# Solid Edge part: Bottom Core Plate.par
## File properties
Author: davee
Template: Normal.par
Last saved by: davee
Revision: 15
Application: Solid Edge
Accuracy: 0.990
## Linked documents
Top Core Plate.par
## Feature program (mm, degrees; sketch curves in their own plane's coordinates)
sketch for "ExtrudedProtrusion_3" plane through (0, 2.945, -20) normal (0, 0, -1) x-axis (-1, 0, 0)
extrude "ExtrudedProtrusion_3" add finite 40 along +normal
sketch for "Hole_3" plane through (0, 0, 0) normal (0, 0, 1) x-axis (1, 0, 0)
  hole centre (-58, 26.745) bore radius 2.4585
hole "Hole_3" finite  VBottomAngle = 118 deg; ThreadDepth = 2 mm
sketch for "unnamed Hole 1" plane through (0, 0, 0) normal (0, 0, 1) x-axis (1, 0, 0)
  hole centre (-58, -22.4) bore radius 2.4585
hole "unnamed Hole 1" finite
sketch for "unnamed Hole 2" plane through (0, 0, 0) normal (0, 0, 1) x-axis (1, 0, 0)
  hole centre (58, -22.4) bore radius 2.4585
hole "unnamed Hole 2" finite
sketch for "unnamed Hole 3" plane through (0, 0, 0) normal (0, 0, 1) x-axis (1, 0, 0)
  hole centre (58, 26.745) bore radius 2.4585
hole "unnamed Hole 3" finite
sketch for "unnamed Hole 4" plane through (0, 0, 0) normal (0, 0, 1) x-axis (1, 0, 0)
  hole centre (19, 1.955) bore radius 5.25
hole "unnamed Hole 4" finite
pattern "unnamed Pattern 1" of "Hole_3", "unnamed Hole 1", "unnamed Hole 2", "unnamed Hole 3", "unnamed Hole 4"
sketch for "ExtrudedCutout_1" #1 plane through (0, 2.945, 0) normal (0, 0, 1) x-axis (1, 0, 0)
  circle centre (-46, -16.445) radius 8
sketch for "ExtrudedCutout_1" #2 plane through (0, 2.945, 0) normal (0, 0, 1) x-axis (1, 0, 0)
  circle centre (46, -16.445) radius 8
extrude "ExtrudedCutout_1" cut finite 92.075 along -normal
sketch for "Hole_8" plane through (0, 0, 0) normal (0, 0, 1) x-axis (1, 0, 0)
  hole centre (0, 4.5) bore radius 3
hole "Hole_8" diameter 6 finite
sketch for "Hole_9" plane through (0, 2.945, -20) normal (0, 0, 1) x-axis (-1, 0, 0)
hole "Hole_9" diameter 10.5 through  CounterBoreDepth = 5.05 mm; VBottomAngle = 118 deg
sketch for "unnamed Hole 5" plane through (0, 2.945, -20) normal (0, 0, 1) x-axis (-1, 0, 0)
hole "unnamed Hole 5" through
pattern "unnamed Pattern 2" of "Hole_9", "unnamed Hole 5"
sketch for "ExtrudedProtrusion_4" #1 plane through (0, 2.945, -20) normal (0, 0, 1) x-axis (-1, 0, 0)
sketch for "ExtrudedProtrusion_4" #2 plane through (0, 2.945, -20) normal (0, 0, 1) x-axis (-1, 0, 0)
  line (-12.1261, 2.3875) -> (-25.8739, 2.3875)
extrude "ExtrudedProtrusion_4" add finite 50 along -normal
Other named dimensions: "CopyConstruction_1": YScale = 1; ZScale = 1
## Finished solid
Body 1: solid body, 27 faces, 59 edges, 32 vertices.
  Faces by surface: plane 13, cylinder 9, cone 5
  Edges by curve: line 36, circle 23
Body 2: solid body, 28 faces, 47 edges, 14 vertices.
  Faces by surface: plane 15, cylinder 13
  Edges by curve: circle 26, line 21
Bounding box of the edges (mm): 130.000 x 63.110 x 70.000, from (-65, -28.61, -70) to (65, 34.5, 0).
Cylindrical faces by radius (mm): R3 x1, R3.25 x4, R5.25 x2, R5.5 x4, R6.9175 x1, R8 x4, R8.5 x4, R10.25 x2
Conical faces (half-angle, radius in mm at the cone's reference point): 59 deg R2.4585 x5
Planar faces by outward normal: +x 3, +y 4, +z 9, -x 3, -y 2, -z 6, oblique 1
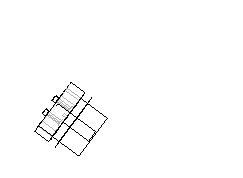
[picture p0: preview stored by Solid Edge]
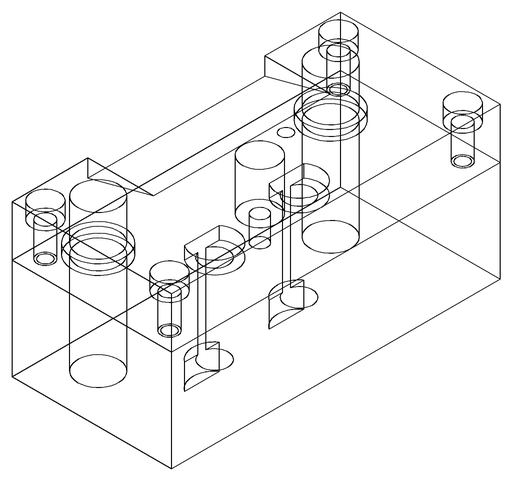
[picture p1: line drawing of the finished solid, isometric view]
